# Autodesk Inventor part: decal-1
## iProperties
Shininess: 64.0
Length Units: 11269
Angle Units: 11279
Time Units: 11290
Mass Units: 11283
Length Display Precision: 3
Angle Display Precision: 2
Compacted: True
Part Number: decal-1
Document SubType Name: Modeling
Created: 2002-12
Designer: deepak
Density: 0.0
Volumn: 0.0
Area: 0.0
PropertySet Name: Model Information
Control State: 0
Master: False
Checked Out: False
Author: deepak
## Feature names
1. Extrusion1
2. Extrusion2
3. Fillet1
